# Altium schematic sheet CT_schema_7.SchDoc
size 251 x 159 mm
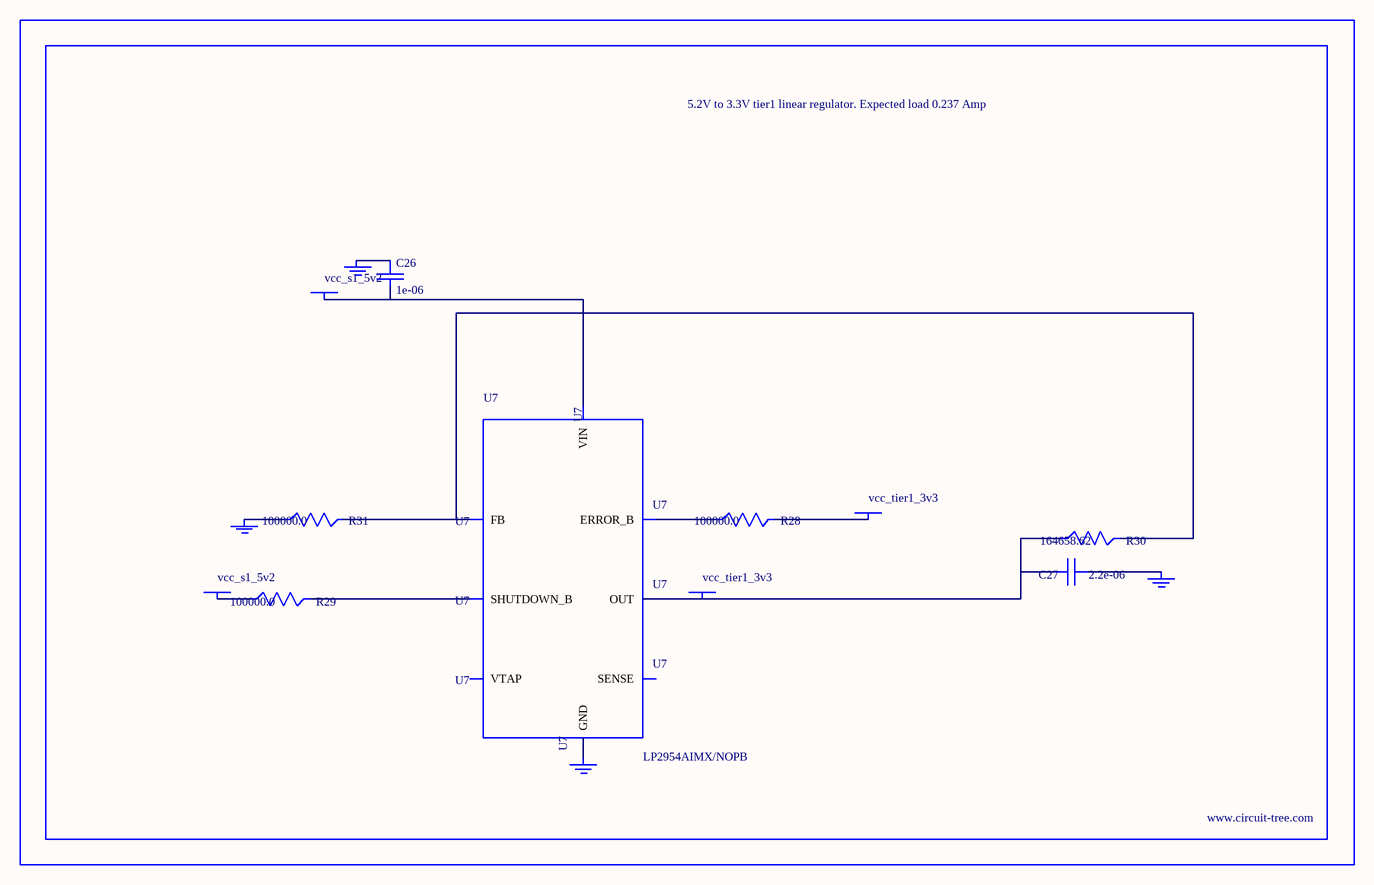
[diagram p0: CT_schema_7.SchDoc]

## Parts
BORDER6  (no value)
C26  1e-06  [EXV-9B]
C27  2.2e-06  [EXV-9B]
GND_INSTANCE_6_0  (no value)
GND_INSTANCE_6_1  (no value)
GND_INSTANCE_6_2  (no value)
GND_INSTANCE_6_3  (no value)
POWER_INSTANCE_6_0  vcc_s1_5v2
POWER_INSTANCE_6_1  vcc_tier1_3v3
POWER_INSTANCE_6_2  vcc_s1_5v2
POWER_INSTANCE_6_3  vcc_tier1_3v3
R28  100000.0  [R0603]
R29  100000.0  [R0603]
R30  164658.62  [R0603]
R31  100000.0  [R0603]
U7  LP2954AIMX/NOPB  [LP2954]

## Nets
NetC26_1: C26.1 GND_INSTANCE_6_2.0(GND)
NetC26_2: C26.2 POWER_INSTANCE_6_2.0(PWR) U7.8(VIN)
NetC27_1: C27.1 GND_INSTANCE_6_0.0(GND)
NetC27_2: C27.2 POWER_INSTANCE_6_3.0(PWR) R30.1 U7.1(OUT)
NetGND_INSTANCE_6_1_0: GND_INSTANCE_6_1.0(GND) R31.1
NetGND_INSTANCE_6_3_0: GND_INSTANCE_6_3.0(GND) U7.4(GND)
NetPOWER_INSTANCE_6_0_0: POWER_INSTANCE_6_0.0(PWR) R29.1
NetPOWER_INSTANCE_6_1_0: POWER_INSTANCE_6_1.0(PWR) R28.2
NetR28_1: R28.1 U7.5(ERROR_B)
NetR29_2: R29.2 U7.3(SHUTDOWN_B)
NetR30_2: R30.2 R31.2 U7.7(FB)

Not connected (* = marked no-connect by the designer): U7 2(SENSE) 6(VTAP)

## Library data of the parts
BORDER6 = BORDER_PAGE6
C26 = EDK105M050A9BAA
C27 = EDK225M050A9BAA
GND_INSTANCE_6_0-GND_INSTANCE_6_3 = GND
POWER_INSTANCE_6_0-POWER_INSTANCE_6_3 = PWR
R28 R29 R31 = RC0603JR-07100KL
R30 = R30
